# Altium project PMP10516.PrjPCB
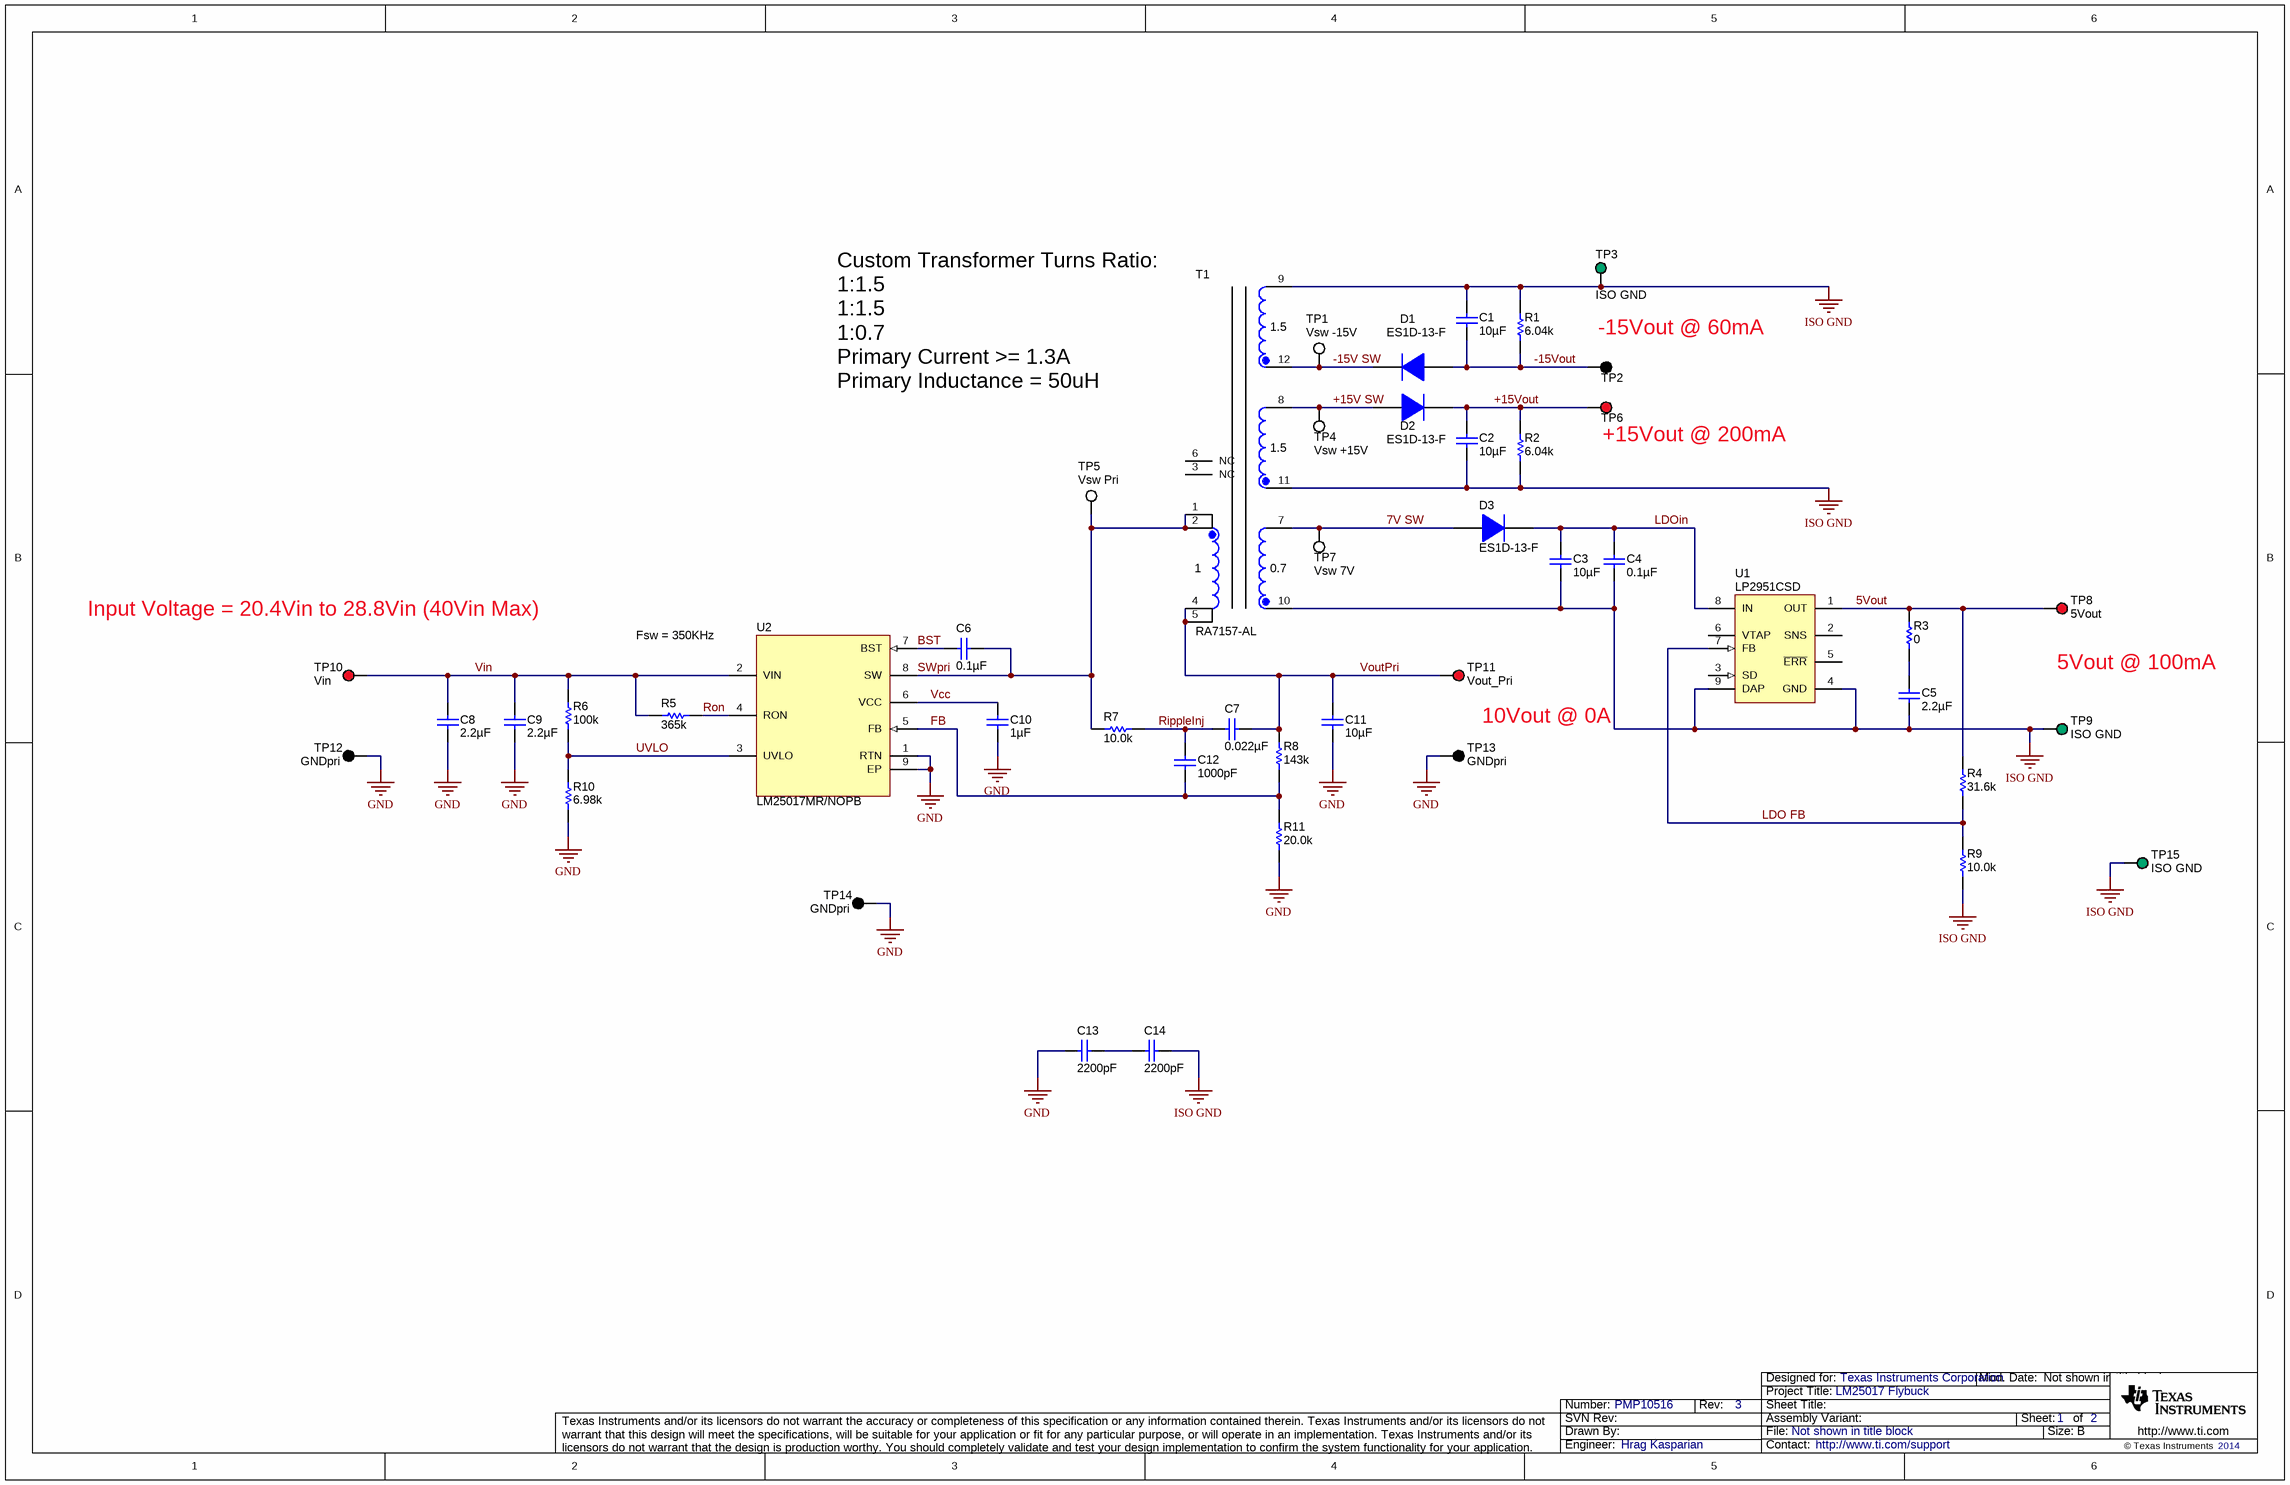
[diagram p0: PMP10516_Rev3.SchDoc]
TID: PMP10516; TechSupport: http://www.ti.com/support; SCH_Rev: 3; PRJ_Title: LM25017 Flybuck; PRJ_Number: PMP10516; PRJ_Engineer: Hrag Kasparian; PRJ_Customer: Texas Instruments Corporation; PCB_Rev: E1; PCB_Layout: Dee LIM; CopyrightYear: 2014
2 sheets, 66 parts. Net scope: global (net labels, ports and power ports of the same name join across sheets).
Board file: PMP10516.PcbDoc
Sheets:
  PMP10516_Rev3.SchDoc
  PMP10516_Hardware_ANSI-B.SchDoc

## Sheet PMP10516_Rev3.SchDoc
size 431 x 279 mm; Date: Not shown in title block; ApprovedBy: Not shown in title block; CheckedBy: Not shown in title block; Author: Not shown in title block; CompanyName: Not shown in title block; Engineer: Not shown in title block; Organization: Not shown in title block; Address1: Not shown in title block; Address2: Not shown in title block; Address3: Not shown in title block; Address4: Not shown in title block; DocumentNumber: 1; Revision: Use project parameter SCH_Rev; SheetNumber: 1; SheetTotal: 2; PageSetup: Record=PageOptions¦CenterHorizontal=True¦CenterVertical=True¦PrintScale=0.96¦XCorrection=1.00¦YCorrection=1.00¦PrintKind=0¦BorderSize=5000000¦LeftOffset=0¦BottomOffset=0¦Orientation=2¦PaperLength=1000¦PaperWidth=1000¦Scale=100¦PaperSource=15¦PrintQuality=600¦MediaType=1¦DitherType=10¦PaperKind=11x17¦PrintScaleMode=1

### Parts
C1  ValueDisplayed: 10µF  [1206]  (hidden comment: GRM31CR71E106KA12L)
C2  ValueDisplayed: 10µF  [1206]  (hidden comment: GRM31CR71E106KA12L)
C3  ValueDisplayed: 10µF  [1206]  (hidden comment: GRM31CR71E106KA12L)
C4  ValueDisplayed: 0.1µF  [0603]  (hidden comment: 06033C104JAT2A)
C5  ValueDisplayed: 2.2µF  [0805_HV]  (hidden comment: C0805C225K8RACTU)
C6  ValueDisplayed: 0.1µF  [0603]  (hidden comment: 06035C104KAT2A)
C7  ValueDisplayed: 0.022µF  [0603]  (hidden comment: C0603C223K5RACTU)
C8  ValueDisplayed: 2.2µF  [1206]  (hidden comment: GRM31CR71H225KA88L)
C9  ValueDisplayed: 2.2µF  [1206]  (hidden comment: GRM31CR71H225KA88L)
C10  ValueDisplayed: 1µF  [0603]  (hidden comment: GRM188R71E105KA12D)
C11  ValueDisplayed: 10µF  [1206]  (hidden comment: GRM31CR71E106KA12L)
C12  ValueDisplayed: 1000pF  [0603]  (hidden comment: C0603C102J5GAC)
C13  ValueDisplayed: 2200pF  [1210]  (hidden comment: VJ1210A222JXGAT5Z)
C14  ValueDisplayed: 2200pF  [1210]  (hidden comment: VJ1210A222JXGAT5Z)
D1  ES1D-13-F  [SMA]
D2  ES1D-13-F  [SMA]
D3  ES1D-13-F  [SMA]
R1  ValueDisplayed: 6.04k  [0603]  (hidden comment: CRCW06036K04FKEA)
R2  ValueDisplayed: 6.04k  [0603]  (hidden comment: CRCW06036K04FKEA)
R3  value 0  [0603]  (hidden comment: CRCW06030000Z0EA)
R4  value 31.6k  [0603]  (hidden comment: CRCW060331K6FKEA)
R5  value 365k  [0603]  (hidden comment: CRCW0603365KFKEA)
R6  value 100k  [0603]  (hidden comment: CRCW0603100KFKEA)
R7  value 10.0k  [0603]  (hidden comment: CRCW060310K0FKEA)
R8  value 143k  [0603]  (hidden comment: CRCW0603143KFKEA)
R9  value 10.0k  [0603]  (hidden comment: CRCW060310K0FKEA)
R10  value 6.98k  [0603]  (hidden comment: CRCW06036K98FKEA)
R11  value 20.0k  [0603]  (hidden comment: CRCW060320K0FKEA)
T1  RA7157-AL  [RA7157-AL]
TP1  Vsw -15V  [Keystone5012]
TP2  5011  [Keystone5011]  (value not drawn)
TP3  ISO GND  [Keystone5126]
TP4  Vsw +15V  [Keystone5012]
TP5  Vsw Pri  [Keystone5012]
TP6  5010  [Keystone5010]  (value not drawn)
TP7  Vsw 7V  [Keystone5012]
TP8  5Vout  [Keystone5010]
TP9  ISO GND  [Keystone5126]
TP10  Vin  [Keystone5010]
TP11  Vout_Pri  [Keystone5010]
TP12  GNDpri  [Keystone5011]
TP13  GNDpri  [Keystone5011]
TP14  GNDpri  [Keystone5011]
TP15  ISO GND  [Keystone5126]
U1  LP2951CSD  [SDC08A]
U2  LM25017MR/NOPB  [DDA0008B_N]

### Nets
GND: C8.2 C9.2 C10.2 C11.2 C13.2 R10.1 R11.1 TP12.1 TP13.1 TP14.1 U2.1(RTN) U2.9(EP)
ISO GND: C1.1 C2.2 C3.2 C4.2 C5.2 C14.1 R1.2 R2.1 R9.1 T1.9 T1.10 T1.11 TP3.1 TP9.1 TP15.1 U1.4(GND) U1.9(DAP)
5Vout: R3.2 R4.2 TP8.1 U1.1(OUT)
7V SW: D3.2(A) T1.7 TP7.1
+15V SW: D2.2(A) T1.8 TP4.1
+15Vout: C2.1 D2.1(K) R2.2 TP6.1
-15V SW: D1.1(K) T1.12 TP1.1
-15Vout: C1.2 D1.2(A) R1.1 TP2.1
BST: C6.2 U2.7(BST)
FB: C12.2 R8.1 R11.2 U2.5(FB)
LDO FB: R4.1 R9.2 U1.7(FB)
LDOin: C3.1 C4.1 D3.1(K) U1.8(IN)
RippleInj: C7.2 C12.1 R7.2
Ron: R5.2 U2.4(RON)
SWpri: C6.1 R7.1 T1.1 T1.2 TP5.1 U2.8(SW)
UVLO: R6.1 R10.2 U2.3(UVLO)
Vcc: C10.1 U2.6(VCC)
Vin: C8.1 C9.1 R5.1 R6.2 TP10.1 U2.2(VIN)
VoutPri: C7.1 C11.1 R8.2 T1.4 T1.5 TP11.1
NetC5_1: C5.1 R3.1
NetC13_1: C13.1 C14.2

Not connected (* = marked no-connect by the designer): T1 3(NC) 6(NC); U1 2(SNS) 3(SD) 5(~{ERR}) 6(VTAP)

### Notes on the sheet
- -15Vout @ 60mA
- (near T1) Custom Transformer Turns Ratio:
  1:1.5
  1:1.5
  1:0.7
  Primary Current >= 1.3A
  Primary Inductance = 50uH
- (near TP6) +15Vout @ 200mA
- Input Voltage = 20.4Vin to 28.8Vin (40Vin Max)
- (near U2) Fsw = 350KHz
- 5Vout @ 100mA
- 10Vout @ 0A

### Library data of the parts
C1-C3 C11 = GRM31CR71E106KA12L: CAP, CERM, 10uF, 25V, +/-10%, X7R, 1206; Manufacturer: MuRata; Polarized: N; CompType: Capacitor; U/M: EA; Cap_F: 0.00001; Tolerance_%: 10; Value1: Unknown; VDC_V: 25; TaMin_C: -55; TaMax_C: 125; Cap_Case: 2220
C4 = 06033C104JAT2A: CAP, CERM, 0.1uF, 25V, +/-5%, X7R, 0603; Manufacturer: AVX; Polarized: N; CompType: Capacitor; U/M: EA; Cap_F: 0.0000001; Tolerance_%: 5; ESR_Ohm: 0.05; Value1: 0.05 ohm; VDC_V: 25; TaMin_C: -55; TaMax_C: 125
C5 = C0805C225K8RACTU: CAP, CERM, 2.2uF, 10V, +/-10%, X7R, 0805; Manufacturer: Kemet; Polarized: N; CompType: Capacitor; U/M: EA; Cap_F: 0.0000022; Tolerance_%: 10; ESR_Ohm: 0.008; Value1: 0.008 ohm; IRMS_A: 15.55; TaMin_C: -55; TaMax_C: 125; Cap_Case: 0805
C6 = 06035C104KAT2A: CAP, CERM, 0.1uF, 50V, +/-10%, X7R, 0603; Manufacturer: AVX; Polarized: N; CompType: Capacitor; U/M: EA; Cap_F: 0.0000001; Tolerance_%: 10; Value1: Unknown; VDC_V: 50; TaMin_C: -55; TaMax_C: 125
C7 = C0603C223K5RACTU: CAP, CERM, 0.022uF, 50V, +/-10%, X7R, 0603; Manufacturer: Kemet; Polarized: N; CompType: Capacitor; U/M: EA; Cap_F: 0.000000022; Tolerance_%: 10; Value1: Unknown; VDC_V: 50; TaMin_C: -55; TaMax_C: 125
C8 C9 = GRM31CR71H225KA88L: CAP, CERM, 2.2uF, 50V, +/-10%, X7R, 1206; Manufacturer: MuRata; Polarized: N; CompType: Capacitor; U/M: EA; Cap_F: 0.0000022; Tolerance_%: 10; Value1: Unknown; VDC_V: 50; TaMin_C: -55; TaMax_C: 125
C10 = GRM188R71E105KA12D: CAP, CERM, 1uF, 25V, +/-10%, X7R, 0603; Manufacturer: MuRata; Polarized: N; CompType: Capacitor; U/M: EA; Cap_F: 0.000001; Tolerance_%: 10; Value1: Unknown; VDC_V: 25; TaMin_C: -55; TaMax_C: 125
C12 = C0603C102J5GAC: CAP, CERM, 1000pF, 50V, +/-5%, C0G/NP0, 0603; Manufacturer: Kemet; Polarized: N; CompType: Capacitor; U/M: EA; Cap_F: 0.000000001; Tolerance_%: 5; Value1: Unknown; VDC_V: 50; TaMin_C: -55; TaMax_C: 125
C13 C14 = VJ1210A222JXGAT5Z: CAP, CERM, 2200 pF, 1000 V, +/- 5%, C0G/NP0, 1210; Manufacturer: Vishay-Vitramon; Polarized: N; CompType: Capacitor; Value: 2200pF; U/M: EA; Cap_F: 0.0000000022; Tolerance_%: 5; Value1: Unknown; VDC_V: 1000; Value2: 1000V; TaMin_C: -55; TaMax_C: 125
D1-D3 = ES1D-13-F: Diode, Ultrafast, 200V, 1A, SMA; Manufacturer: Diodes Inc.; U/M: EA; Vf_V: 0.92; Value2: 0.92V; Io_A: 1; Vr_V: 200; TJmax_C: 150; RJC_CperW: 25
R1 R2 = CRCW06036K04FKEA: RES, 6.04 k, 1%, 0.1 W, 0603; Manufacturer: Vishay-Dale; CompType: Resistor; Value: 6.04k; Res_ohm: 6040; Value_Code: 6k04; Tolerance_%: 1; Power_W: 0.1; Value2: 0.1W; VDC_V: 75; TempCo: 100 ppm/C; EIA_Code: E96; U/M: EA
R3 = CRCW06030000Z0EA: RES, 0 ohm, 5%, 0.1W, 0603; Manufacturer: Vishay-Dale; CompType: Resistor; Value_Code: 0000; Tolerance_%: 5; Power_W: 0.1; VDC_V: 75; TempCo: 200 ppm/C; EIA_Code: E24; U/M: EA
R4 = CRCW060331K6FKEA: RES, 31.6k ohm, 1%, 0.1W, 0603; Manufacturer: Vishay-Dale; CompType: Resistor; U/M: EA; Res_ohm: 31600; Value_Code: 31k6; Tolerance_%: 1; Power_W: 0.1; VDC_V: 75; TempCo: 100 ppm/C; EIA_Code: E96
R5 = CRCW0603365KFKEA: RES, 365k ohm, 1%, 0.1W, 0603; Manufacturer: Vishay-Dale; CompType: Resistor; Res_ohm: 365000; Tolerance_%: 1; Power_W: 0.1; VDC_V: 75; TempCo: 100 ppm/C; EIA_Code: E96; U/M: EA
R6 = CRCW0603100KFKEA: RES, 100k ohm, 1%, 0.1W, 0603; Manufacturer: Vishay-Dale; CompType: Resistor; Res_ohm: 100000; Tolerance_%: 1; Power_W: 0.1; VDC_V: 75; TempCo: 100 ppm/C; EIA_Code: E96; U/M: EA
R7 = CRCW060310K0FKEA: RES, 10.0k ohm, 1%, 0.1W, 0603; Manufacturer: Vishay-Dale; CompType: Resistor; Res_ohm: 10000; Value_Code: 10k0; Tolerance_%: 1; Power_W: 0.1; VDC_V: 75; TempCo: 100 ppm/C; EIA_Code: E96; U/M: EA
R8 = CRCW0603143KFKEA: RES, 143k ohm, 1%, 0.1W, 0603; Manufacturer: Vishay-Dale; CompType: Resistor; Res_ohm: 143000; Tolerance_%: 1; Power_W: 0.1; VDC_V: 75; TempCo: 100 ppm/C; EIA_Code: E96; U/M: EA
R9 = CRCW060310K0FKEA: RES, 10.0k ohm, 1%, 0.1W, 0603; Manufacturer: Vishay-Dale; CompType: Resistor; U/M: EA; Res_ohm: 10000; Value_Code: 10k0; Tolerance_%: 1; Power_W: 0.1; VDC_V: 75; TempCo: 100 ppm/C; EIA_Code: E96
R10 = CRCW06036K98FKEA: RES, 6.98k ohm, 1%, 0.1W, 0603; Manufacturer: Vishay-Dale; CompType: Resistor; Res_ohm: 6980; Value_Code: 6k98; Tolerance_%: 1; Power_W: 0.1; VDC_V: 75; TempCo: 100 ppm/C; EIA_Code: E96; U/M: EA
R11 = CRCW060320K0FKEA: RES, 20.0k ohm, 1%, 0.1W, 0603; Manufacturer: Vishay-Dale; CompType: Resistor; Res_ohm: 20000; Value_Code: 20k0; Tolerance_%: 1; Power_W: 0.1; VDC_V: 75; TempCo: 100 ppm/C; EIA_Code: E96; U/M: EA
T1 = RA7157-AL_V2: 1:1.5:1.5:0.7 Turns Ratio Transformer; Manufacturer: Coilcraft; SymbolCreator: a0412036; U/M: EA
TP1 TP4 TP5 TP7 = 5012: Test Point, Multipurpose, White, TH; Manufacturer: Keystone; CompType: Test Point Loop; U/M: EA
TP2 TP12-TP14 = 5011: Test Point, Multipurpose, Black, TH; Manufacturer: Keystone; CompType: Test Point Loop; U/M: EA
TP3 TP9 TP15 = 5126: Test Point, Multipurpose, Green, TH; Manufacturer: Keystone; SymbolCreator: a0412235; CompType: Test Point Loop; U/M: EA
TP6 TP8 TP10 TP11 = 5010: Test Point, Multipurpose, Red, TH; Manufacturer: Keystone; CompType: Test Point Loop; U/M: EA
U1 = LP2951CSD: Series of Adjustable Micropower Voltage Regulators, 8-pin LLP; Manufacturer: Texas Instruments; PackageTopMarking: NS*UZXYTT*2951ACB; PowerWise: N; CompType: LDO IC
U2 = LM25017MR/NOPB: 48V, 650mA Constant On-Time Synchronous Buck Regulator, DDA0008B; Manufacturer: Texas Instruments; SymbolCreator: a0412235; CompType: IC; U/M: EA

## Sheet PMP10516_Hardware_ANSI-B.SchDoc
size 431 x 279 mm; Date: Not shown in title block; ApprovedBy: Not shown in title block; CheckedBy: Not shown in title block; Author: Not shown in title block; CompanyName: Not shown in title block; Engineer: Not shown in title block; Organization: Not shown in title block; Address1: Not shown in title block; Address2: Not shown in title block; Address3: Not shown in title block; Address4: Not shown in title block; DocumentNumber: 2; Revision: Use project parameter SCH_Rev; SheetNumber: 2; SheetTotal: 2; PageSetup: Record=PageOptions¦CenterHorizontal=True¦CenterVertical=True¦PrintScale=1.00¦XCorrection=1.00¦YCorrection=1.00¦PrintKind=0¦BorderSize=5000000¦LeftOffset=0¦BottomOffset=0¦Orientation=2¦PaperLength=1000¦PaperWidth=1000¦Scale=100¦PaperSource=15¦PrintQuality=600¦MediaType=1¦DitherType=10¦PaperKind=Letter¦PrintScaleMode=1
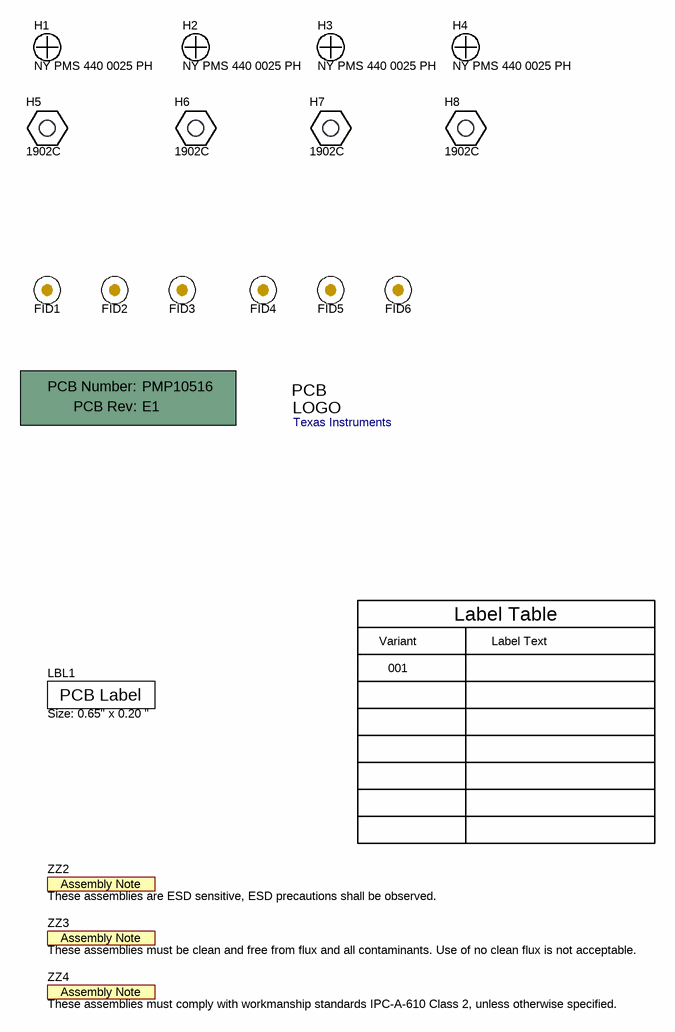
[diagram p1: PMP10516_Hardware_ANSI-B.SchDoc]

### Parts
!PCB1  Printed Circuit Board  (value not drawn)  (mechanical)
FID1  Fiducial  [Fiducial10-20]  (value not drawn)
FID2  Fiducial  [Fiducial10-20]  (value not drawn)
FID3  Fiducial  [Fiducial10-20]  (value not drawn)
FID4  Fiducial  [Fiducial10-20]  (value not drawn)
FID5  Fiducial  [Fiducial10-20]  (value not drawn)
FID6  Fiducial  [Fiducial10-20]  (value not drawn)
H1  NY PMS 440 0025 PH  [NY PMS 440 0025 PH]
H2  NY PMS 440 0025 PH  [NY PMS 440 0025 PH]
H3  NY PMS 440 0025 PH  [NY PMS 440 0025 PH]
H4  NY PMS 440 0025 PH  [NY PMS 440 0025 PH]
H5  1902C  [Keystone_1902C]
H6  1902C  [Keystone_1902C]
H7  1902C  [Keystone_1902C]
H8  1902C  [Keystone_1902C]
LBL1  Size: 0.65" x 0.20 "  [Label_650x200]
Logo1  Texas Instruments  [TI_Symbol_Overlay_Medium]  (no BOM)
ZZ2  These assemblies are ESD sensitive, ESD precautions shall be observed.  [AssemblyNote]  (no BOM)
ZZ3  These assemblies must be clean and free from flux and all contaminants. Use of no clean flux is not acceptable.  [AssemblyNote]  (no BOM)
ZZ4  These assemblies must comply with workmanship standards IPC-A-610 Class 2, unless otherwise specified.  [AssemblyNote]  (no BOM)

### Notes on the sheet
- Variant
- Label Table
- Label Text
- 001

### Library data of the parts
!PCB1 = PCB: Manufacturer: Any; PartNumber: PMP10516; SymbolCreator: a0412235
FID1-FID6 = Fiducial: Fiducial mark.  There is nothing to buy or mount.; SymbolCreator: codlsc
H1-H4 = NY PMS 440 0025 PH: Machine Screw, Round, #4-40 x 1/4, Nylon, Philips panhead; Manufacturer: B&F Fastener Supply; CompType: Hardware; SymbolCreator: codlsc; U/M: EA
H5-H8 = 1902C: Standoff, Hex, 0.5"L #4-40 Nylon; Manufacturer: Keystone; CompType: Hardware; SymbolCreator: a0412235
LBL1 = THT-14-423-10: Thermal Transfer Printable Labels, 0.650" W x 0.200" H - 10,000 per roll; Manufacturer: Brady; SymbolCreator: a0412235; CompType: Label
Logo1 = TI_Logo: Texas Instrument Corporate Signature; SymbolCreator: a0412235
ZZ2-ZZ4 = AssemblyNote: SymbolCreator: codlsc

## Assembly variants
001: all parts fitted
